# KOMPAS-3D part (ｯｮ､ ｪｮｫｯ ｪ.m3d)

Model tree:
1. Эскиз:2
2. Операция выдавливания:1
     Расстояние 1 = 35; Угол 1 = 4
3. Эскиз:3
4. Вырезать элемент выдавливания:1
     Расстояние 2 = 35; Угол 2 = 1.91; Расстояние 1 = 10
5. Оболочка:2
     Толщина стенки 2 = 1
6. Эскиз:8
7. Вырезать элемент выдавливания:4
     Расстояние 2 = 11.1672; Расстояние 1 = 11.1672
8. Эскиз:10
9. Операция выдавливания:4
     Расстояние 1 = 1; Угол 2 = 1.98
10. Эскиз:16
11. Операция выдавливания:9
     Расстояние 1 = 2; Расстояние 2 = 1; Угол 2 = 4
12. Эскиз:17
13. Операция выдавливания:10
     Расстояние 1 = 3; Расстояние 2 = 15; Угол 2 = 4
14. Эскиз:18
15. Операция выдавливания:11
     Расстояние 1 = 1; Расстояние 2 = 15; Угол 2 = 4
16. Скругление:1
     Радиус = 1
17. Скругление:2
     Радиус = 1
18. Скругление:3
     Радиус = 1
19. Эскиз:22
20. Вырезать элемент выдавливания:8
     Расстояние 1 = 15
21. Эскиз:23
22. Вырезать элемент выдавливания:9
     Расстояние 1 = 10
23. Эскиз:24
24. Вырезать элемент выдавливания:10
     Расстояние 1 = 15
